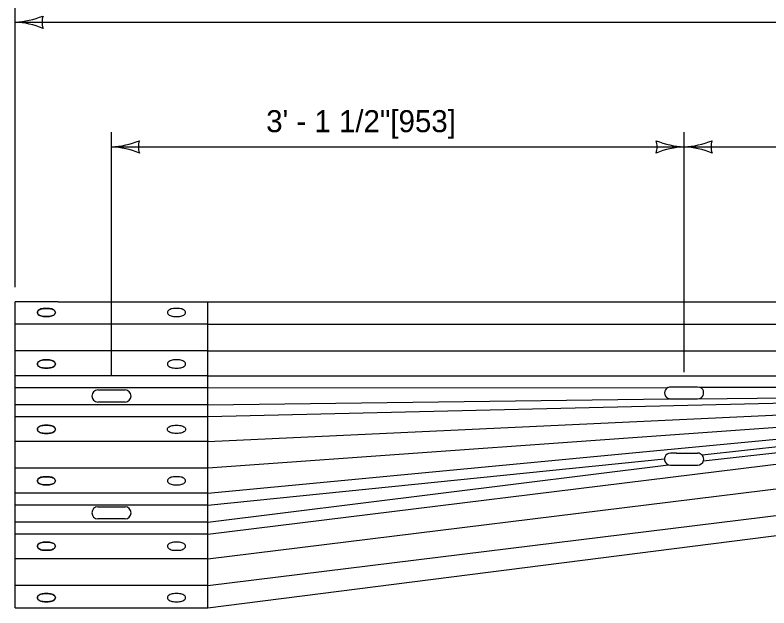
# Model space of a CAD drawing. Extents: x 49991 to 50160, y 49948 to 50051.
# Drawn here: x 50012.117 to 50014.17, y 49992.648 to 49994.263 of the extents above; entities that cross this region are included whole.
import ezdxf

# ---------------------------------------------------------------- set-up
doc = ezdxf.new("R2010")
doc.units = 0
for name, color, linetype in [('Level 1', 7, 'Continuous'), ('Level 2', 7, 'Continuous'), ('Level 3', 7, 'Continuous')]:
    doc.layers.add(name, color=color, linetype=linetype)

msp = doc.modelspace()

# ---------------------------------------------------------------- linework, layer by layer
at = {"layer": 'Level 1'}
for p, q in [((50012.1168, 49992.6481), (50012.1168, 49993.4814)), ((50012.234, 49993.4814), (50015.7668, 49993.4812)), ((50012.6417, 49992.6481), (50012.6417, 49993.4814)), ((50012.207, 49993.4637), (50012.1972, 49993.4637)), ((50012.1972, 49993.4637), (50012.207, 49993.4637)), ((50012.5613, 49993.4637), (50012.5515, 49993.4637)), ((50012.1972, 49993.4416), (50012.207, 49993.4416)), ((50012.207, 49993.4416), (50012.1972, 49993.4416)), ((50012.5515, 49993.4416), (50012.5613, 49993.4416)), ((50012.6417, 49993.4206), (50012.1168, 49993.4206)), ((50012.6417, 49993.4206), (50015.7668, 49993.4206)), ((50012.6417, 49993.3481), (50012.1168, 49993.3481)), ((50012.6417, 49993.3481), (50015.7668, 49993.3478)), ((50012.207, 49993.3235), (50012.1972, 49993.3235)), ((50012.1972, 49993.3235), (50012.207, 49993.3235)), ((50012.5613, 49993.3235), (50012.5515, 49993.3235)), ((50012.1972, 49993.3014), (50012.207, 49993.3014)), ((50012.207, 49993.3014), (50012.1972, 49993.3014)), ((50012.5515, 49993.3014), (50012.5613, 49993.3014)), ((50012.6417, 49993.2803), (50012.1168, 49993.2803)), ((50012.6417, 49993.2803), (50015.7668, 49993.2808)), ((50012.6417, 49993.2477), (50012.1168, 49993.2477)), ((50012.3423, 49993.2417), (50012.4162, 49993.2417)), ((50012.6417, 49993.2477), (50013.8943, 49993.2482)), ((50013.9019, 49993.25), (50013.9757, 49993.25)), ((50013.9757, 49993.2172), (50015.2419, 49993.2352)), ((50013.9811, 49993.2491), (50015.7668, 49993.2485)), ((50015.2419, 49993.2294), (50012.6417, 49993.1687)), ((50012.6417, 49993.1011), (50015.2419, 49993.2221)), ((50012.6417, 49993.2014), (50013.8983, 49993.2174)), ((50015.2419, 49993.2146), (50012.6417, 49993.0283)), ((50013.9019, 49993.2172), (50013.9757, 49993.2172)), ((50012.641, 49993.2014), (50012.1168, 49993.2014)), ((50012.4162, 49993.2088), (50012.3423, 49993.2088)), ((50012.6417, 49992.9608), (50015.2419, 49993.2073)), ((50013.9883, 49993.0651), (50015.2419, 49993.201)), ((50013.9906, 49993.0485), (50015.2419, 49993.1879)), ((50012.6424, 49993.1687), (50012.1168, 49993.1687)), ((50012.6417, 49992.8492), (50015.2419, 49993.1697)), ((50012.1972, 49993.1454), (50012.207, 49993.1454)), ((50012.207, 49993.1454), (50012.1972, 49993.1454)), ((50012.5515, 49993.1454), (50012.5613, 49993.1454)), ((50012.207, 49993.1234), (50012.1972, 49993.1234)), ((50012.1972, 49993.1234), (50012.207, 49993.1234)), ((50012.5613, 49993.1234), (50012.5515, 49993.1234)), ((50012.6437, 49993.1011), (50012.1168, 49993.1011)), ((50012.6417, 49992.7816), (50015.2419, 49993.1024)), ((50013.9184, 49993.0696), (50013.9019, 49993.0696)), ((50013.9184, 49993.0696), (50013.9757, 49993.0696)), ((50012.6417, 49992.928), (50013.8855, 49993.0539)), ((50012.6417, 49993.0283), (50012.1168, 49993.0283)), ((50012.6417, 49992.8819), (50013.896, 49993.0379)), ((50012.6417, 49992.7088), (50015.2419, 49993.0299)), ((50013.896, 49993.0379), (50013.9019, 49993.0368)), ((50013.9019, 49993.0368), (50013.9757, 49993.0368)), ((50012.207, 49993.0052), (50012.1972, 49993.0052)), ((50012.1972, 49993.0052), (50012.207, 49993.0052)), ((50012.5613, 49993.0052), (50012.5515, 49993.0052)), ((50012.1972, 49992.9832), (50012.207, 49992.9832)), ((50012.207, 49992.9832), (50012.1972, 49992.9832)), ((50012.5515, 49992.9832), (50012.5613, 49992.9832)), ((50012.6417, 49992.6481), (50015.2419, 49992.9795)), ((50012.6417, 49992.9608), (50012.1168, 49992.9608)), ((50012.6417, 49992.928), (50012.1168, 49992.928)), ((50012.3423, 49992.9234), (50012.4162, 49992.9234)), ((50012.4162, 49992.8906), (50012.3423, 49992.8906)), ((50012.6417, 49992.8819), (50012.1168, 49992.8819)), ((50012.6417, 49992.8492), (50012.1168, 49992.8492)), ((50012.207, 49992.8272), (50012.1972, 49992.8272)), ((50012.1972, 49992.8272), (50012.207, 49992.8272)), ((50012.5613, 49992.8272), (50012.5515, 49992.8272)), ((50012.1972, 49992.8051), (50012.207, 49992.8051)), ((50012.207, 49992.8051), (50012.1972, 49992.8051)), ((50012.5515, 49992.8051), (50012.5613, 49992.8051)), ((50012.6417, 49992.7816), (50012.1168, 49992.7816)), ((50012.6417, 49992.7088), (50012.1168, 49992.7088)), ((50012.207, 49992.687), (50012.1972, 49992.687)), ((50012.1972, 49992.687), (50012.207, 49992.687)), ((50012.5613, 49992.687), (50012.5515, 49992.687)), ((50012.1972, 49992.6649), (50012.207, 49992.6649)), ((50012.207, 49992.6649), (50012.1972, 49992.6649)), ((50012.5515, 49992.6649), (50012.5613, 49992.6649))]:
    msp.add_line(p, q, dxfattribs=at)
for points in [[(50012.234, 49993.4814), (50012.1168, 49993.4814)], [(50012.1972, 49993.4637), (50012.1937, 49993.4635), (50012.1904, 49993.463), (50012.1873, 49993.4622), (50012.1845, 49993.4611), (50012.1821, 49993.4597), (50012.1801, 49993.4582), (50012.1787, 49993.4564), (50012.1778, 49993.4546), (50012.1777, 49993.4545)], [(50012.1777, 49993.4545), (50012.1778, 49993.4546), (50012.1787, 49993.4564), (50012.1801, 49993.4582), (50012.1821, 49993.4597), (50012.1845, 49993.4611), (50012.1873, 49993.4622), (50012.1904, 49993.463), (50012.1937, 49993.4635), (50012.1972, 49993.4637)], [(50012.2264, 49993.4545), (50012.2264, 49993.4546), (50012.2255, 49993.4564), (50012.2241, 49993.4582), (50012.2221, 49993.4597), (50012.2197, 49993.4611), (50012.2168, 49993.4622), (50012.2137, 49993.463), (50012.2104, 49993.4635), (50012.207, 49993.4637)], [(50012.207, 49993.4637), (50012.2104, 49993.4635), (50012.2137, 49993.463), (50012.2168, 49993.4622), (50012.2197, 49993.4611), (50012.2221, 49993.4597), (50012.2241, 49993.4582), (50012.2255, 49993.4564), (50012.2264, 49993.4546), (50012.2264, 49993.4545)], [(50012.5515, 49993.4637), (50012.5481, 49993.4635), (50012.5448, 49993.463), (50012.5416, 49993.4622), (50012.5388, 49993.4611), (50012.5364, 49993.4597), (50012.5344, 49993.4582), (50012.533, 49993.4564), (50012.5321, 49993.4546), (50012.5321, 49993.4545)], [(50012.5808, 49993.4545), (50012.5807, 49993.4546), (50012.5798, 49993.4564), (50012.5784, 49993.4582), (50012.5764, 49993.4597), (50012.574, 49993.4611), (50012.5712, 49993.4622), (50012.5681, 49993.463), (50012.5648, 49993.4635), (50012.5613, 49993.4637)], [(50012.1777, 49993.4545), (50012.1775, 49993.4527), (50012.1778, 49993.4507), (50012.1787, 49993.4489), (50012.1801, 49993.4471), (50012.1821, 49993.4456), (50012.1845, 49993.4442), (50012.1873, 49993.4431), (50012.1904, 49993.4423), (50012.1937, 49993.4418), (50012.1972, 49993.4416)], [(50012.1972, 49993.4416), (50012.1937, 49993.4418), (50012.1904, 49993.4423), (50012.1873, 49993.4431), (50012.1845, 49993.4442), (50012.1821, 49993.4456), (50012.1801, 49993.4471), (50012.1787, 49993.4489), (50012.1778, 49993.4507), (50012.1775, 49993.4527), (50012.1777, 49993.4545)], [(50012.207, 49993.4416), (50012.2104, 49993.4418), (50012.2137, 49993.4423), (50012.2168, 49993.4431), (50012.2197, 49993.4442), (50012.2221, 49993.4456), (50012.2241, 49993.4471), (50012.2255, 49993.4489), (50012.2264, 49993.4507), (50012.2267, 49993.4527), (50012.2264, 49993.4545)], [(50012.2264, 49993.4545), (50012.2267, 49993.4527), (50012.2264, 49993.4507), (50012.2255, 49993.4489), (50012.2241, 49993.4471), (50012.2221, 49993.4456), (50012.2197, 49993.4442), (50012.2168, 49993.4431), (50012.2137, 49993.4423), (50012.2104, 49993.4418), (50012.207, 49993.4416)], [(50012.5321, 49993.4545), (50012.5318, 49993.4527), (50012.5321, 49993.4507), (50012.533, 49993.4489), (50012.5344, 49993.4471), (50012.5364, 49993.4456), (50012.5388, 49993.4442), (50012.5416, 49993.4431), (50012.5448, 49993.4423), (50012.5481, 49993.4418), (50012.5515, 49993.4416)], [(50012.5613, 49993.4416), (50012.5648, 49993.4418), (50012.5681, 49993.4423), (50012.5712, 49993.4431), (50012.574, 49993.4442), (50012.5764, 49993.4456), (50012.5784, 49993.4471), (50012.5798, 49993.4489), (50012.5807, 49993.4507), (50012.581, 49993.4527), (50012.5808, 49993.4545)], [(50012.1972, 49993.3235), (50012.1937, 49993.3233), (50012.1904, 49993.3228), (50012.1873, 49993.322), (50012.1845, 49993.3209), (50012.1821, 49993.3195), (50012.1801, 49993.318), (50012.1787, 49993.3162), (50012.1778, 49993.3144), (50012.1775, 49993.3125), (50012.1778, 49993.3105), (50012.1787, 49993.3087), (50012.1801, 49993.3069), (50012.1821, 49993.3054), (50012.1845, 49993.304), (50012.1873, 49993.3029), (50012.1904, 49993.3021), (50012.1937, 49993.3016), (50012.1972, 49993.3014)], [(50012.1972, 49993.3014), (50012.1937, 49993.3016), (50012.1904, 49993.3021), (50012.1873, 49993.3029), (50012.1845, 49993.304), (50012.1821, 49993.3054), (50012.1801, 49993.3069), (50012.1787, 49993.3087), (50012.1778, 49993.3105), (50012.1775, 49993.3125), (50012.1778, 49993.3144), (50012.1787, 49993.3162), (50012.1801, 49993.318), (50012.1821, 49993.3195), (50012.1845, 49993.3209), (50012.1873, 49993.322), (50012.1904, 49993.3228), (50012.1937, 49993.3233), (50012.1972, 49993.3235)], [(50012.207, 49993.3014), (50012.2104, 49993.3016), (50012.2137, 49993.3021), (50012.2168, 49993.3029), (50012.2197, 49993.304), (50012.2221, 49993.3054), (50012.2241, 49993.3069), (50012.2255, 49993.3087), (50012.2264, 49993.3105), (50012.2267, 49993.3125), (50012.2264, 49993.3144), (50012.2255, 49993.3162), (50012.2241, 49993.318), (50012.2221, 49993.3195), (50012.2197, 49993.3209), (50012.2168, 49993.322), (50012.2137, 49993.3228), (50012.2104, 49993.3233), (50012.207, 49993.3235)], [(50012.207, 49993.3235), (50012.2104, 49993.3233), (50012.2137, 49993.3228), (50012.2168, 49993.322), (50012.2197, 49993.3209), (50012.2221, 49993.3195), (50012.2241, 49993.318), (50012.2255, 49993.3162), (50012.2264, 49993.3144), (50012.2267, 49993.3125), (50012.2264, 49993.3105), (50012.2255, 49993.3087), (50012.2241, 49993.3069), (50012.2221, 49993.3054), (50012.2197, 49993.304), (50012.2168, 49993.3029), (50012.2137, 49993.3021), (50012.2104, 49993.3016), (50012.207, 49993.3014)], [(50012.5515, 49993.3235), (50012.5481, 49993.3233), (50012.5448, 49993.3228), (50012.5416, 49993.322), (50012.5388, 49993.3209), (50012.5364, 49993.3195), (50012.5344, 49993.318), (50012.533, 49993.3162), (50012.5321, 49993.3144), (50012.5318, 49993.3125), (50012.5321, 49993.3105), (50012.533, 49993.3087), (50012.5344, 49993.3069), (50012.5364, 49993.3054), (50012.5388, 49993.304), (50012.5416, 49993.3029), (50012.5448, 49993.3021), (50012.5481, 49993.3016), (50012.5515, 49993.3014)], [(50012.5613, 49993.3014), (50012.5648, 49993.3016), (50012.5681, 49993.3021), (50012.5712, 49993.3029), (50012.574, 49993.304), (50012.5764, 49993.3054), (50012.5784, 49993.3069), (50012.5798, 49993.3087), (50012.5807, 49993.3105), (50012.581, 49993.3125), (50012.5807, 49993.3144), (50012.5798, 49993.3162), (50012.5784, 49993.318), (50012.5764, 49993.3195), (50012.574, 49993.3209), (50012.5712, 49993.322), (50012.5681, 49993.3228), (50012.5648, 49993.3233), (50012.5613, 49993.3235)], [(50013.8944, 49993.2482), (50013.8997, 49993.2499), (50013.9019, 49993.25)], [(50013.9757, 49993.25), (50013.9811, 49993.2491), (50013.9832, 49993.2482)], [(50013.8946, 49993.2189), (50013.8999, 49993.2173), (50013.9019, 49993.2172)], [(50013.9757, 49993.2172), (50013.9811, 49993.2181), (50013.985, 49993.2201)], [(50012.1972, 49993.1234), (50012.1937, 49993.1236), (50012.1904, 49993.1241), (50012.1873, 49993.1249), (50012.1845, 49993.126), (50012.1821, 49993.1273), (50012.1801, 49993.1289), (50012.1787, 49993.1306), (50012.1778, 49993.1325), (50012.1775, 49993.1344), (50012.1777, 49993.1362)], [(50012.1777, 49993.1362), (50012.1775, 49993.1344), (50012.1778, 49993.1325), (50012.1787, 49993.1306), (50012.1801, 49993.1289), (50012.1821, 49993.1273), (50012.1845, 49993.126), (50012.1873, 49993.1249), (50012.1904, 49993.1241), (50012.1937, 49993.1236), (50012.1972, 49993.1234)], [(50012.1777, 49993.1362), (50012.1778, 49993.1363), (50012.1787, 49993.1382), (50012.1801, 49993.1399), (50012.1821, 49993.1415), (50012.1845, 49993.1429), (50012.1873, 49993.144), (50012.1904, 49993.1448), (50012.1937, 49993.1453), (50012.1972, 49993.1454)], [(50012.1972, 49993.1454), (50012.1937, 49993.1453), (50012.1904, 49993.1448), (50012.1873, 49993.144), (50012.1845, 49993.1429), (50012.1821, 49993.1415), (50012.1801, 49993.1399), (50012.1787, 49993.1382), (50012.1778, 49993.1363), (50012.1777, 49993.1362)], [(50012.207, 49993.1454), (50012.2104, 49993.1453), (50012.2137, 49993.1448), (50012.2168, 49993.144), (50012.2197, 49993.1429), (50012.2221, 49993.1415), (50012.2241, 49993.1399), (50012.2255, 49993.1382), (50012.2264, 49993.1363), (50012.2264, 49993.1362)], [(50012.2264, 49993.1362), (50012.2264, 49993.1363), (50012.2255, 49993.1382), (50012.2241, 49993.1399), (50012.2221, 49993.1415), (50012.2197, 49993.1429), (50012.2168, 49993.144), (50012.2137, 49993.1448), (50012.2104, 49993.1453), (50012.207, 49993.1454)], [(50012.2264, 49993.1362), (50012.2267, 49993.1344), (50012.2264, 49993.1325), (50012.2255, 49993.1306), (50012.2241, 49993.1289), (50012.2221, 49993.1273), (50012.2197, 49993.126), (50012.2168, 49993.1249), (50012.2137, 49993.1241), (50012.2104, 49993.1236), (50012.207, 49993.1234)], [(50012.207, 49993.1234), (50012.2104, 49993.1236), (50012.2137, 49993.1241), (50012.2168, 49993.1249), (50012.2197, 49993.126), (50012.2221, 49993.1273), (50012.2241, 49993.1289), (50012.2255, 49993.1306), (50012.2264, 49993.1325), (50012.2267, 49993.1344), (50012.2264, 49993.1362)], [(50012.5515, 49993.1234), (50012.5481, 49993.1236), (50012.5448, 49993.1241), (50012.5416, 49993.1249), (50012.5388, 49993.126), (50012.5364, 49993.1273), (50012.5344, 49993.1289), (50012.533, 49993.1306), (50012.5321, 49993.1325), (50012.5318, 49993.1344), (50012.5321, 49993.1362)], [(50012.5321, 49993.1362), (50012.5321, 49993.1363), (50012.533, 49993.1382), (50012.5344, 49993.1399), (50012.5364, 49993.1415), (50012.5388, 49993.1429), (50012.5416, 49993.144), (50012.5448, 49993.1448), (50012.5481, 49993.1453), (50012.5515, 49993.1454)], [(50012.5613, 49993.1454), (50012.5648, 49993.1453), (50012.5681, 49993.1448), (50012.5712, 49993.144), (50012.574, 49993.1429), (50012.5764, 49993.1415), (50012.5784, 49993.1399), (50012.5798, 49993.1382), (50012.5807, 49993.1363), (50012.5808, 49993.1362)], [(50012.5808, 49993.1362), (50012.581, 49993.1344), (50012.5807, 49993.1325), (50012.5798, 49993.1306), (50012.5784, 49993.1289), (50012.5764, 49993.1273), (50012.574, 49993.126), (50012.5712, 49993.1249), (50012.5681, 49993.1241), (50012.5648, 49993.1236), (50012.5613, 49993.1234)], [(50013.9019, 49993.0696), (50013.8965, 49993.0687), (50013.8927, 49993.0668)], [(50013.9757, 49993.0368), (50013.981, 49993.0377), (50013.9857, 49993.0402), (50013.9894, 49993.0442), (50013.9908, 49993.0468), (50013.9917, 49993.0496)], [(50012.1972, 49993.0052), (50012.1937, 49993.0051), (50012.1904, 49993.0046), (50012.1873, 49993.0038), (50012.1845, 49993.0027), (50012.1821, 49993.0013), (50012.1801, 49992.9997), (50012.1787, 49992.998), (50012.1778, 49992.9961), (50012.1775, 49992.9942), (50012.1778, 49992.9923), (50012.1787, 49992.9904), (50012.1801, 49992.9887), (50012.1821, 49992.9871), (50012.1845, 49992.9858), (50012.1873, 49992.9847), (50012.1904, 49992.9839), (50012.1937, 49992.9834), (50012.1972, 49992.9832)], [(50012.1972, 49992.9832), (50012.1937, 49992.9834), (50012.1904, 49992.9839), (50012.1873, 49992.9847), (50012.1845, 49992.9858), (50012.1821, 49992.9871), (50012.1801, 49992.9887), (50012.1787, 49992.9904), (50012.1778, 49992.9923), (50012.1775, 49992.9942), (50012.1778, 49992.9961), (50012.1787, 49992.998), (50012.1801, 49992.9997), (50012.1821, 49993.0013), (50012.1845, 49993.0027), (50012.1873, 49993.0038), (50012.1904, 49993.0046), (50012.1937, 49993.0051), (50012.1972, 49993.0052)], [(50012.207, 49992.9832), (50012.2104, 49992.9834), (50012.2137, 49992.9839), (50012.2168, 49992.9847), (50012.2197, 49992.9858), (50012.2221, 49992.9871), (50012.2241, 49992.9887), (50012.2255, 49992.9904), (50012.2264, 49992.9923), (50012.2267, 49992.9942), (50012.2264, 49992.9961), (50012.2255, 49992.998), (50012.2241, 49992.9997), (50012.2221, 49993.0013), (50012.2197, 49993.0027), (50012.2168, 49993.0038), (50012.2137, 49993.0046), (50012.2104, 49993.0051), (50012.207, 49993.0052)], [(50012.207, 49993.0052), (50012.2104, 49993.0051), (50012.2137, 49993.0046), (50012.2168, 49993.0038), (50012.2197, 49993.0027), (50012.2221, 49993.0013), (50012.2241, 49992.9997), (50012.2255, 49992.998), (50012.2264, 49992.9961), (50012.2267, 49992.9942), (50012.2264, 49992.9923), (50012.2255, 49992.9904), (50012.2241, 49992.9887), (50012.2221, 49992.9871), (50012.2197, 49992.9858), (50012.2168, 49992.9847), (50012.2137, 49992.9839), (50012.2104, 49992.9834), (50012.207, 49992.9832)], [(50012.5515, 49993.0052), (50012.5481, 49993.0051), (50012.5448, 49993.0046), (50012.5416, 49993.0038), (50012.5388, 49993.0027), (50012.5364, 49993.0013), (50012.5344, 49992.9997), (50012.533, 49992.998), (50012.5321, 49992.9961), (50012.5318, 49992.9942), (50012.5321, 49992.9923), (50012.533, 49992.9904), (50012.5344, 49992.9887), (50012.5364, 49992.9871), (50012.5388, 49992.9858), (50012.5416, 49992.9847), (50012.5448, 49992.9839), (50012.5481, 49992.9834), (50012.5515, 49992.9832)], [(50012.5613, 49992.9832), (50012.5648, 49992.9834), (50012.5681, 49992.9839), (50012.5712, 49992.9847), (50012.574, 49992.9858), (50012.5764, 49992.9871), (50012.5784, 49992.9887), (50012.5798, 49992.9904), (50012.5807, 49992.9923), (50012.581, 49992.9942), (50012.5807, 49992.9961), (50012.5798, 49992.998), (50012.5784, 49992.9997), (50012.5764, 49993.0013), (50012.574, 49993.0027), (50012.5712, 49993.0038), (50012.5681, 49993.0046), (50012.5648, 49993.0051), (50012.5613, 49993.0052)], [(50012.1972, 49992.8272), (50012.1937, 49992.827), (50012.1904, 49992.8265), (50012.1873, 49992.8257), (50012.1845, 49992.8246), (50012.1821, 49992.8233), (50012.1801, 49992.8217), (50012.1787, 49992.8199), (50012.1778, 49992.8181), (50012.1777, 49992.818)], [(50012.1777, 49992.818), (50012.1778, 49992.8181), (50012.1787, 49992.8199), (50012.1801, 49992.8217), (50012.1821, 49992.8233), (50012.1845, 49992.8246), (50012.1873, 49992.8257), (50012.1904, 49992.8265), (50012.1937, 49992.827), (50012.1972, 49992.8272)], [(50012.2264, 49992.818), (50012.2264, 49992.8181), (50012.2255, 49992.8199), (50012.2241, 49992.8217), (50012.2221, 49992.8233), (50012.2197, 49992.8246), (50012.2168, 49992.8257), (50012.2137, 49992.8265), (50012.2104, 49992.827), (50012.207, 49992.8272)], [(50012.207, 49992.8272), (50012.2104, 49992.827), (50012.2137, 49992.8265), (50012.2168, 49992.8257), (50012.2197, 49992.8246), (50012.2221, 49992.8233), (50012.2241, 49992.8217), (50012.2255, 49992.8199), (50012.2264, 49992.8181), (50012.2264, 49992.818)], [(50012.5515, 49992.8272), (50012.5481, 49992.827), (50012.5448, 49992.8265), (50012.5416, 49992.8257), (50012.5388, 49992.8246), (50012.5364, 49992.8233), (50012.5344, 49992.8217), (50012.533, 49992.8199), (50012.5321, 49992.8181), (50012.5321, 49992.818)], [(50012.5808, 49992.818), (50012.5807, 49992.8181), (50012.5798, 49992.8199), (50012.5784, 49992.8217), (50012.5764, 49992.8233), (50012.574, 49992.8246), (50012.5712, 49992.8257), (50012.5681, 49992.8265), (50012.5648, 49992.827), (50012.5613, 49992.8272)], [(50012.1777, 49992.818), (50012.1775, 49992.8162), (50012.1778, 49992.8143), (50012.1787, 49992.8124), (50012.1801, 49992.8107), (50012.1821, 49992.8091), (50012.1845, 49992.8077), (50012.1873, 49992.8066), (50012.1904, 49992.8058), (50012.1937, 49992.8053), (50012.1972, 49992.8051)], [(50012.1972, 49992.8051), (50012.1937, 49992.8053), (50012.1904, 49992.8058), (50012.1873, 49992.8066), (50012.1845, 49992.8077), (50012.1821, 49992.8091), (50012.1801, 49992.8107), (50012.1787, 49992.8124), (50012.1778, 49992.8143), (50012.1775, 49992.8162), (50012.1777, 49992.818)], [(50012.207, 49992.8051), (50012.2104, 49992.8053), (50012.2137, 49992.8058), (50012.2168, 49992.8066), (50012.2197, 49992.8077), (50012.2221, 49992.8091), (50012.2241, 49992.8107), (50012.2255, 49992.8124), (50012.2264, 49992.8143), (50012.2267, 49992.8162), (50012.2264, 49992.818)], [(50012.2264, 49992.818), (50012.2267, 49992.8162), (50012.2264, 49992.8143), (50012.2255, 49992.8124), (50012.2241, 49992.8107), (50012.2221, 49992.8091), (50012.2197, 49992.8077), (50012.2168, 49992.8066), (50012.2137, 49992.8058), (50012.2104, 49992.8053), (50012.207, 49992.8051)], [(50012.5321, 49992.818), (50012.5318, 49992.8162), (50012.5321, 49992.8143), (50012.533, 49992.8124), (50012.5344, 49992.8107), (50012.5364, 49992.8091), (50012.5388, 49992.8077), (50012.5416, 49992.8066), (50012.5448, 49992.8058), (50012.5481, 49992.8053), (50012.5515, 49992.8051)], [(50012.5613, 49992.8051), (50012.5648, 49992.8053), (50012.5681, 49992.8058), (50012.5712, 49992.8066), (50012.574, 49992.8077), (50012.5764, 49992.8091), (50012.5784, 49992.8107), (50012.5798, 49992.8124), (50012.5807, 49992.8143), (50012.581, 49992.8162), (50012.5808, 49992.818)], [(50012.1972, 49992.687), (50012.1937, 49992.6868), (50012.1904, 49992.6863), (50012.1873, 49992.6855), (50012.1845, 49992.6844), (50012.1821, 49992.6831), (50012.1801, 49992.6815), (50012.1787, 49992.6797), (50012.1778, 49992.6779), (50012.1775, 49992.676), (50012.1778, 49992.6741), (50012.1787, 49992.6722), (50012.1801, 49992.6705), (50012.1821, 49992.6689), (50012.1845, 49992.6675), (50012.1873, 49992.6664), (50012.1904, 49992.6656), (50012.1937, 49992.6651), (50012.1972, 49992.6649)], [(50012.1972, 49992.6649), (50012.1937, 49992.6651), (50012.1904, 49992.6656), (50012.1873, 49992.6664), (50012.1845, 49992.6675), (50012.1821, 49992.6689), (50012.1801, 49992.6705), (50012.1787, 49992.6722), (50012.1778, 49992.6741), (50012.1775, 49992.676), (50012.1778, 49992.6779), (50012.1787, 49992.6797), (50012.1801, 49992.6815), (50012.1821, 49992.6831), (50012.1845, 49992.6844), (50012.1873, 49992.6855), (50012.1904, 49992.6863), (50012.1937, 49992.6868), (50012.1972, 49992.687)], [(50012.207, 49992.6649), (50012.2104, 49992.6651), (50012.2137, 49992.6656), (50012.2168, 49992.6664), (50012.2197, 49992.6675), (50012.2221, 49992.6689), (50012.2241, 49992.6705), (50012.2255, 49992.6722), (50012.2264, 49992.6741), (50012.2267, 49992.676), (50012.2264, 49992.6779), (50012.2255, 49992.6797), (50012.2241, 49992.6815), (50012.2221, 49992.6831), (50012.2197, 49992.6844), (50012.2168, 49992.6855), (50012.2137, 49992.6863), (50012.2104, 49992.6868), (50012.207, 49992.687)], [(50012.207, 49992.687), (50012.2104, 49992.6868), (50012.2137, 49992.6863), (50012.2168, 49992.6855), (50012.2197, 49992.6844), (50012.2221, 49992.6831), (50012.2241, 49992.6815), (50012.2255, 49992.6797), (50012.2264, 49992.6779), (50012.2267, 49992.676), (50012.2264, 49992.6741), (50012.2255, 49992.6722), (50012.2241, 49992.6705), (50012.2221, 49992.6689), (50012.2197, 49992.6675), (50012.2168, 49992.6664), (50012.2137, 49992.6656), (50012.2104, 49992.6651), (50012.207, 49992.6649)], [(50012.5515, 49992.687), (50012.5481, 49992.6868), (50012.5448, 49992.6863), (50012.5416, 49992.6855), (50012.5388, 49992.6844), (50012.5364, 49992.6831), (50012.5344, 49992.6815), (50012.533, 49992.6797), (50012.5321, 49992.6779), (50012.5318, 49992.676), (50012.5321, 49992.6741), (50012.533, 49992.6722), (50012.5344, 49992.6705), (50012.5364, 49992.6689), (50012.5388, 49992.6675), (50012.5416, 49992.6664), (50012.5448, 49992.6656), (50012.5481, 49992.6651), (50012.5515, 49992.6649)], [(50012.5613, 49992.6649), (50012.5648, 49992.6651), (50012.5681, 49992.6656), (50012.5712, 49992.6664), (50012.574, 49992.6675), (50012.5764, 49992.6689), (50012.5784, 49992.6705), (50012.5798, 49992.6722), (50012.5807, 49992.6741), (50012.581, 49992.676), (50012.5807, 49992.6779), (50012.5798, 49992.6797), (50012.5784, 49992.6815), (50012.5764, 49992.6831), (50012.574, 49992.6844), (50012.5712, 49992.6855), (50012.5681, 49992.6863), (50012.5648, 49992.6868), (50012.5613, 49992.687)], [(50012.1168, 49992.6481), (50012.6417, 49992.6481)]]:
    msp.add_lwpolyline(points, dxfattribs=at)
for centre, start, end in [((50012.3423, 49993.2252), 90, 270), ((50012.4162, 49993.2252), 270, 90), ((50013.9019, 49993.2336), 117.1386, 243.6106), ((50013.9757, 49993.2336), 304.6387, 62.8614), ((50013.9757, 49993.0532), 347.308, 90), ((50013.9019, 49993.0532), 124.0204, 249.0228), ((50012.3423, 49992.907), 90, 270), ((50012.4162, 49992.907), 270, 90)]:
    msp.add_arc(centre, 0.0164, start, end, dxfattribs=at)
at = {"layer": 'Level 3'}
for p, q in [((50012.1168, 49993.5214), (50012.1168, 49994.2833)), ((50012.1168, 49994.2433), (50015.7668, 49994.2433)), ((50012.3792, 49993.2817), (50012.3792, 49993.9437)), ((50013.9388, 49993.29), (50013.9388, 49993.9437)), ((50012.3792, 49993.9037), (50013.9388, 49993.9037)), ((50013.9388, 49993.9037), (50015.5043, 49993.9037))]:
    msp.add_line(p, q, dxfattribs=at)
for centre, radius, start, end in [((50012.1053, 49994.476), 0.233, 272.8273, 292.0772), ((50012.245, 49994.2433), 0.0548, 162.1388, 197.8612), ((50012.1076, 49994.0212), 0.2223, 67.456, 87.6395), ((50012.3678, 49994.1364), 0.233, 272.8273, 292.0772), ((50012.5075, 49993.9037), 0.0548, 162.1388, 197.8612), ((50013.948, 49994.1259), 0.2223, 247.456, 267.6395), ((50013.8106, 49993.9037), 0.0548, 342.1388, 17.8612), ((50013.9273, 49994.1364), 0.233, 272.8273, 292.0772), ((50014.067, 49993.9037), 0.0548, 162.1388, 197.8612), ((50012.3701, 49993.6816), 0.2223, 67.456, 87.6395), ((50013.9503, 49993.671), 0.233, 92.8273, 112.0772), ((50013.9296, 49993.6816), 0.2223, 67.456, 87.6395)]:
    msp.add_arc(centre, radius, start, end, dxfattribs=at)

# ---------------------------------------------------------------- texts
at = {"layer": 'Level 2'}
msp.add_text('3\' - 1 1/2"[953]', height=0.06, dxfattribs=at).set_placement((50012.8007, 49993.9437))

doc.saveas('drawing.dxf')
